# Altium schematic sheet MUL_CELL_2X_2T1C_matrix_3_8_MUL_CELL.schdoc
size 420 x 297 mm; Symbol: Drawing-Symbol_A4; @Project Name: Inverted_MAML_6x6; @Page Count: 1; @Update Date: 2026-06-07; @Create Date: 2026-06-07; @Schematic Name: Schematic2; @Page No: 1; @Page Name: P1; Company: EasyEDA.com; Version: V1.0; Page Size: A4; Drawn: Olle Welin; Device: Drawing-Symbol_A4; @Create Time: 20:01:01; @Update Time: 20:01:01; Border: 1; Width: 1655; Height: 1170; Region Start: 1; X Region Count: 6; Y Region Count: 4; Blade Width: 10; Title Block Position: 3
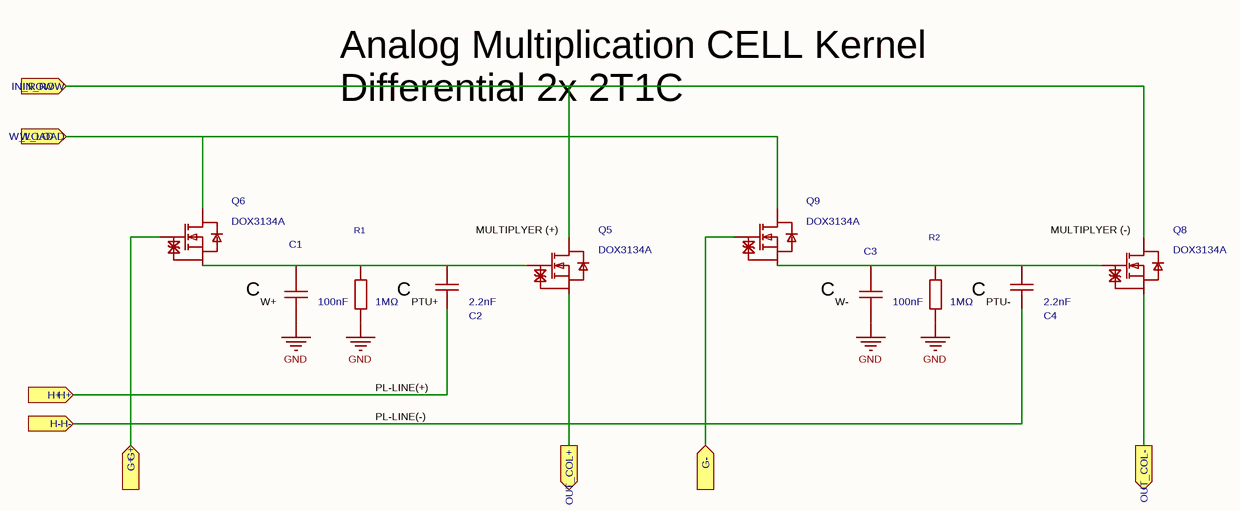
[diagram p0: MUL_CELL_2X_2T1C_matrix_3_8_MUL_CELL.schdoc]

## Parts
C1  100nF  [C0402]
C2  2.2nF  [C0402]
C3  100nF  [C0402]
C4  2.2nF  [C0402]
Q5  DOX3134A  [SOT-323-3_L2.1-W1.3-P1.30-LS2.3-BR]
Q6  DOX3134A  [SOT-323-3_L2.1-W1.3-P1.30-LS2.3-BR]
Q8  DOX3134A  [SOT-323-3_L2.1-W1.3-P1.30-LS2.3-BR]
Q9  DOX3134A  [SOT-323-3_L2.1-W1.3-P1.30-LS2.3-BR]
R1  1MΩ  [R0402]
R2  1MΩ  [R0402]

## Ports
G+ (in), G- (in), H+ (in), H- (in), IN_ROW (in), OUT_COL+ (out), OUT_COL- (out), W_LOAD (in)

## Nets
GND: C1.1 C3.1 R1.1 R2.1
G+: Q6.1(G) ; port G+
G-: Q9.1(G) ; port G-
H+: C2.1 ; port H+
H-: C4.1 ; port H-
IN_ROW: Q5.3(D) Q8.3(D) ; port IN_ROW
OUT_COL+: Q5.2(S) ; port OUT_COL+
OUT_COL-: Q8.2(S) ; port OUT_COL-
W_LOAD: Q6.3(D) Q9.3(D) ; port W_LOAD
NetC1_2: C1.2 C2.2 Q5.1(G) Q6.2(S) R1.2
NetC3_2: C3.2 C4.2 Q8.1(G) Q9.2(S) R2.2

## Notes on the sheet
- Analog Multiplication CELL Kernel
  Differential 2x 2T1C
- (near Q5) MULTIPLYER (+)
- (near Q8) MULTIPLYER (-)
- C
- (near C1) W+
- (near C2) PTU+
- (near C3) W-
- (near C4) PTU-
- PL-LINE(+)
- PL-LINE(-)

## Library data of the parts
C1 C3 = CL05B104KO5NNNC: Capacitance:100nF Tolerance:±10% Tolerance:±10% Voltage Rating:16V Temperature Coefficient:X7R; Manufacturer: SAMSUNG(三星); AddInBom: yes; ModelId: b7d13df3e9464d7a99d0651d1a5b4d570819f05c4eef4c71ace90d822a990e87; ModelName: C0402_L1.0-W0.5-H0.5; ModelTransform: 39.37,19.685,0,0,0,0,0,0,0; Tolerance: ±10%; Voltage Rating: 16V; Temperature Coefficient: X7R
C2 C4 = 0402B222K500NT: Capacitance:2.2nF Tolerance:±10% Tolerance:±10% Voltage Rating:50V Temperature Coefficient:X7R; Manufacturer: FH(风华); Add into BOM: yes; 3D Model: b7d13df3e9464d7a99d0651d1a5b4d57; 3D Model Transform: 39.37,19.685,0,0,0,0,0,0,0; Tolerance: ±10%; Voltage Rating: 50V; Temperature Coefficient: X7R; ModelName: C0402_L1.0-W0.5-H0.5
Q5 Q6 Q8 Q9 = DOX3134A: Number:1 N-channel Drain to Source Voltage:20V Current - Continuous Drain(Id):900mA RDS(on):120Ω@4.5V Pd - Power Dissipation:220mW Gate Threshold Voltage (Vgs(th)):600mV Gate Charge(Qg):1nC@4.5V Input Capacitance(Ciss):63pF Reverse Transfer Capacitance (C; Manufacturer: DOINGTER(杜因特); 3D Model: 4ef9dcfb8d16439f88dacdf9bd184e54; 3D Model Transform: 90.551,78.74,0,0,0,0,0,0,0; Drain to Source Voltage: 20V; Current - Continuous Drain(Id): 900mA; Pd - Power Dissipation: 220mW; Gate Threshold Voltage (Vgs(th)): 600mV; Input Capacitance(Ciss): 63pF; Reverse Transfer Capacitance (Crss@Vds): 12pF; Output Capacitance(Coss): 23pF; AddInBom: yes
R1 R2 = 0402WGF1004TCE: Type:Thick Film Resistor Resistance:1MΩ Tolerance:±1% Tolerance:±1% Power(Watts):62.5mW Voltage-Supply(Max):50V Temperature Coefficient:±100ppm/℃ Temperature Coefficient:±100ppm/℃ Operating Temperature:-55℃~+155℃ Operating Temperature:-55℃~+155℃; Manufacturer: UNI-ROYAL(厚声); AddInBom: yes; ModelId: efdecb7dae4442949d28eecaf748420f0819f05c4eef4c71ace90d822a990e87; ModelName: R0402_L1.0-W0.5-H0.4; ModelTransform: 39.37,19.685,0,0,0,0,0,0,0; Tolerance: ±1%; Power(Watts): 62.5mW; Voltage-Supply(Max): 50V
